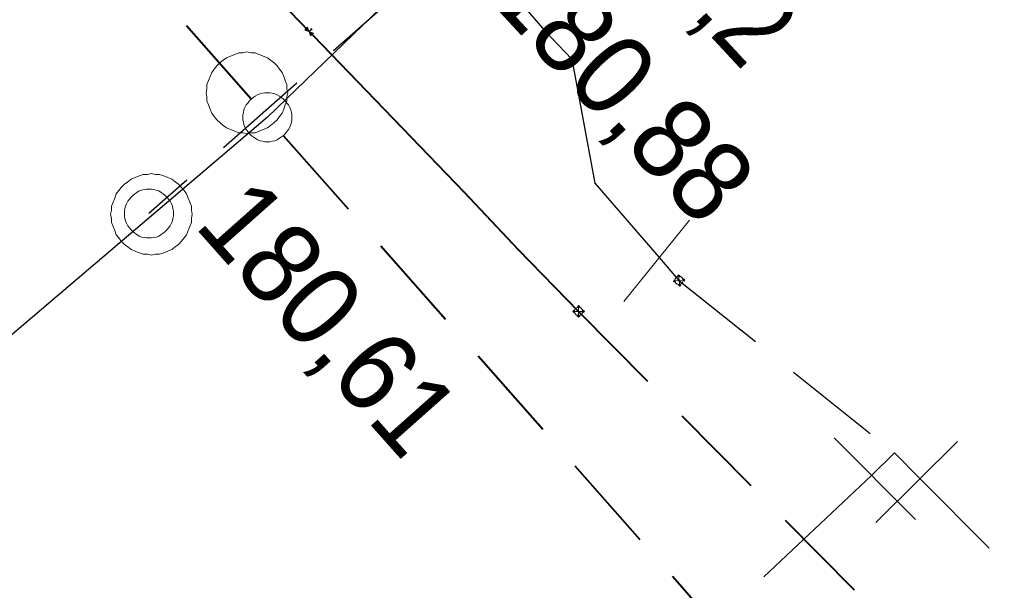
# Model space of a CAD drawing. Extents: x -740851 to -738888, y -1041382 to -1040235.
# Drawn here: x -739704.31 to -739692.27, y -1040578.08 to -1040571.08 of the extents above; entities that cross this region are included whole.
import ezdxf

# ---------------------------------------------------------------- set-up
doc = ezdxf.new("R2010")
doc.units = 0
doc.header["$LTSCALE"] = 0.4
doc.linetypes.add('MEDIUM_DASHED', pattern=[4.5, 3, -1.5])
for name, color, linetype, lineweight in [('18', 7, 'Continuous', 13), ('20', 7, 'MEDIUM_DASHED', 25), ('8', 7, 'Continuous', 13)]:
    doc.layers.add(name, color=color, linetype=linetype, lineweight=lineweight)

msp = doc.modelspace()

# ---------------------------------------------------------------- linework, layer by layer
at = {"layer": '18', "lineweight": 25}
msp.add_line((-739699.51, -1040570.57), (-739701.28, -1040572.28), dxfattribs=at)
at = {"layer": '18', "linetype": 'MEDIUM_DASHED', "lineweight": 40}
msp.add_lwpolyline([(-739669.06, -1040610.98), (-739674.7, -1040603.39), (-739681.24, -1040595.01), (-739703.155, -1040570.156)], dxfattribs=at)
at = {"layer": '18'}
for points in [[(-739701.03, -1040571.98), (-739701.04, -1040571.93), (-739701.04, -1040571.88), (-739701.06, -1040571.83), (-739701.08, -1040571.78), (-739701.1, -1040571.73), (-739701.13, -1040571.69), (-739701.16, -1040571.65), (-739701.2, -1040571.61), (-739701.24, -1040571.58), (-739701.28, -1040571.55), (-739701.33, -1040571.53), (-739701.38, -1040571.51), (-739701.43, -1040571.49), (-739701.48, -1040571.49), (-739701.53, -1040571.48), (-739701.58, -1040571.49), (-739701.63, -1040571.49), (-739701.68, -1040571.51), (-739701.73, -1040571.53), (-739701.78, -1040571.55), (-739701.82, -1040571.58), (-739701.86, -1040571.61), (-739701.9, -1040571.65), (-739701.93, -1040571.69), (-739701.96, -1040571.73), (-739701.98, -1040571.78), (-739702, -1040571.83), (-739702.02, -1040571.88), (-739702.02, -1040571.93), (-739702.03, -1040571.98), (-739702.02, -1040572.03), (-739702.02, -1040572.08), (-739702, -1040572.13), (-739701.98, -1040572.18), (-739701.96, -1040572.23), (-739701.93, -1040572.27), (-739701.9, -1040572.31), (-739701.86, -1040572.35), (-739701.82, -1040572.38), (-739701.78, -1040572.41), (-739701.73, -1040572.43), (-739701.68, -1040572.45), (-739701.63, -1040572.47), (-739701.58, -1040572.47), (-739701.53, -1040572.48), (-739701.48, -1040572.47), (-739701.43, -1040572.47), (-739701.38, -1040572.45), (-739701.33, -1040572.43), (-739701.28, -1040572.41), (-739701.24, -1040572.38), (-739701.2, -1040572.35), (-739701.16, -1040572.31), (-739701.13, -1040572.27), (-739701.1, -1040572.23), (-739701.08, -1040572.18), (-739701.06, -1040572.13), (-739701.04, -1040572.08), (-739701.04, -1040572.03)], [(-739700.98, -1040572.28), (-739700.98, -1040572.25), (-739700.986, -1040572.22), (-739700.992, -1040572.19), (-739701.004, -1040572.16), (-739701.022, -1040572.13), (-739701.04, -1040572.106), (-739701.058, -1040572.082), (-739701.082, -1040572.058), (-739701.106, -1040572.04), (-739701.13, -1040572.022), (-739701.16, -1040572.004), (-739701.19, -1040571.992), (-739701.22, -1040571.986), (-739701.25, -1040571.98), (-739701.28, -1040571.98), (-739701.31, -1040571.98), (-739701.34, -1040571.986), (-739701.37, -1040571.992), (-739701.4, -1040572.004), (-739701.43, -1040572.022), (-739701.454, -1040572.04), (-739701.478, -1040572.058), (-739701.502, -1040572.082), (-739701.52, -1040572.106), (-739701.538, -1040572.13), (-739701.556, -1040572.16), (-739701.568, -1040572.19), (-739701.574, -1040572.22), (-739701.58, -1040572.25), (-739701.58, -1040572.28), (-739701.58, -1040572.31), (-739701.574, -1040572.34), (-739701.568, -1040572.37), (-739701.556, -1040572.4), (-739701.538, -1040572.43), (-739701.52, -1040572.454), (-739701.502, -1040572.478), (-739701.478, -1040572.502), (-739701.454, -1040572.52), (-739701.43, -1040572.538), (-739701.4, -1040572.556), (-739701.37, -1040572.568), (-739701.34, -1040572.574), (-739701.31, -1040572.58), (-739701.28, -1040572.58), (-739701.25, -1040572.58), (-739701.22, -1040572.574), (-739701.19, -1040572.568), (-739701.16, -1040572.556), (-739701.13, -1040572.538), (-739701.106, -1040572.52), (-739701.082, -1040572.502), (-739701.058, -1040572.478), (-739701.04, -1040572.454), (-739701.022, -1040572.43), (-739701.004, -1040572.4), (-739700.992, -1040572.37), (-739700.986, -1040572.34), (-739700.98, -1040572.31)], [(-739702.2, -1040573.47), (-739702.21, -1040573.42), (-739702.21, -1040573.37), (-739702.23, -1040573.32), (-739702.25, -1040573.27), (-739702.27, -1040573.22), (-739702.3, -1040573.18), (-739702.33, -1040573.14), (-739702.37, -1040573.1), (-739702.41, -1040573.07), (-739702.45, -1040573.04), (-739702.5, -1040573.02), (-739702.55, -1040573), (-739702.6, -1040572.98), (-739702.65, -1040572.98), (-739702.7, -1040572.97), (-739702.75, -1040572.98), (-739702.8, -1040572.98), (-739702.85, -1040573), (-739702.9, -1040573.02), (-739702.95, -1040573.04), (-739702.99, -1040573.07), (-739703.03, -1040573.1), (-739703.07, -1040573.14), (-739703.1, -1040573.18), (-739703.13, -1040573.22), (-739703.15, -1040573.27), (-739703.17, -1040573.32), (-739703.19, -1040573.37), (-739703.19, -1040573.42), (-739703.2, -1040573.47), (-739703.19, -1040573.52), (-739703.19, -1040573.57), (-739703.17, -1040573.62), (-739703.15, -1040573.67), (-739703.13, -1040573.72), (-739703.1, -1040573.76), (-739703.07, -1040573.8), (-739703.03, -1040573.84), (-739702.99, -1040573.87), (-739702.95, -1040573.9), (-739702.9, -1040573.92), (-739702.85, -1040573.94), (-739702.8, -1040573.96), (-739702.75, -1040573.96), (-739702.7, -1040573.97), (-739702.65, -1040573.96), (-739702.6, -1040573.96), (-739702.55, -1040573.94), (-739702.5, -1040573.92), (-739702.45, -1040573.9), (-739702.41, -1040573.87), (-739702.37, -1040573.84), (-739702.33, -1040573.8), (-739702.3, -1040573.76), (-739702.27, -1040573.72), (-739702.25, -1040573.67), (-739702.23, -1040573.62), (-739702.21, -1040573.57), (-739702.21, -1040573.52)], [(-739702.43, -1040573.46), (-739702.43, -1040573.43), (-739702.436, -1040573.4), (-739702.442, -1040573.37), (-739702.454, -1040573.34), (-739702.472, -1040573.31), (-739702.49, -1040573.286), (-739702.508, -1040573.262), (-739702.532, -1040573.238), (-739702.556, -1040573.22), (-739702.58, -1040573.202), (-739702.61, -1040573.184), (-739702.64, -1040573.172), (-739702.67, -1040573.166), (-739702.7, -1040573.16), (-739702.73, -1040573.16), (-739702.76, -1040573.16), (-739702.79, -1040573.166), (-739702.82, -1040573.172), (-739702.85, -1040573.184), (-739702.88, -1040573.202), (-739702.904, -1040573.22), (-739702.928, -1040573.238), (-739702.952, -1040573.262), (-739702.97, -1040573.286), (-739702.988, -1040573.31), (-739703.006, -1040573.34), (-739703.018, -1040573.37), (-739703.024, -1040573.4), (-739703.03, -1040573.43), (-739703.03, -1040573.46), (-739703.03, -1040573.49), (-739703.024, -1040573.52), (-739703.018, -1040573.55), (-739703.006, -1040573.58), (-739702.988, -1040573.61), (-739702.97, -1040573.634), (-739702.952, -1040573.658), (-739702.928, -1040573.682), (-739702.904, -1040573.7), (-739702.88, -1040573.718), (-739702.85, -1040573.736), (-739702.82, -1040573.748), (-739702.79, -1040573.754), (-739702.76, -1040573.76), (-739702.73, -1040573.76), (-739702.7, -1040573.76), (-739702.67, -1040573.754), (-739702.64, -1040573.748), (-739702.61, -1040573.736), (-739702.58, -1040573.718), (-739702.556, -1040573.7), (-739702.532, -1040573.682), (-739702.508, -1040573.658), (-739702.49, -1040573.634), (-739702.472, -1040573.61), (-739702.454, -1040573.58), (-739702.442, -1040573.55), (-739702.436, -1040573.52), (-739702.43, -1040573.49)]]:
    msp.add_lwpolyline(points, close=True, dxfattribs=at)
at = {"layer": '18', "lineweight": 25}
msp.add_lwpolyline([(-739701.28, -1040572.28), (-739707.2, -1040577.32), (-739710.924, -1040580.488)], dxfattribs=at)
at = {"layer": '20'}
msp.add_lwpolyline([(-739674.14, -1040548.21), (-739688.774, -1040561.14), (-739702.73, -1040573.46)], dxfattribs=at)
at = {"layer": '8'}
for p, q in [((-739700.769, -1040571.23), (-739700.734, -1040571.195)), ((-739696.913, -1040574.54), (-739696.112, -1040573.54)), ((-739696.246, -1040574.21), (-739696.258, -1040574.225)), ((-739696.246, -1040574.21), (-739696.23, -1040574.35)), ((-739696.246, -1040574.21), (-739696.23, -1040574.222)), ((-739696.308, -1040574.288), (-739696.168, -1040574.272)), ((-739696.308, -1040574.288), (-739696.296, -1040574.272)), ((-739696.308, -1040574.288), (-739696.293, -1040574.3)), ((-739696.23, -1040574.35), (-739696.246, -1040574.338)), ((-739696.23, -1040574.35), (-739696.218, -1040574.335)), ((-739696.168, -1040574.272), (-739696.184, -1040574.26)), ((-739696.168, -1040574.272), (-739696.18, -1040574.288)), ((-739697.469, -1040574.589), (-739697.483, -1040574.603)), ((-739697.469, -1040574.589), (-739697.469, -1040574.731)), ((-739697.469, -1040574.589), (-739697.455, -1040574.604)), ((-739697.54, -1040574.66), (-739697.526, -1040574.646)), ((-739697.54, -1040574.66), (-739697.398, -1040574.66)), ((-739697.54, -1040574.66), (-739697.526, -1040574.674)), ((-739697.398, -1040574.66), (-739697.413, -1040574.674)), ((-739697.398, -1040574.66), (-739697.412, -1040574.646)), ((-739697.469, -1040574.731), (-739697.484, -1040574.716)), ((-739697.469, -1040574.731), (-739697.455, -1040574.717)), ((-739693.344, -1040577.21), (-739694.337, -1040576.21)), ((-739693.826, -1040577.247), (-739692.826, -1040576.253))]:
    msp.add_line(p, q, dxfattribs=at)
at = {"layer": '8', "lineweight": 25}
for p, q in [((-739696.48, -1040574), (-739696.24, -1040574.28)), ((-739693.601, -1040576.393), (-739693.88, -1040576.67)), ((-739693.88, -1040576.67), (-739695.2, -1040577.915))]:
    msp.add_line(p, q, dxfattribs=at)
at = {"layer": '8', "lineweight": 40}
for points in [[(-739703.68, -1040568.1), (-739703.46, -1040568.39), (-739702.71, -1040569.21), (-739702.32, -1040569.62), (-739700.77, -1040571.23)], [(-739700.77, -1040571.23), (-739700.72, -1040571.28), (-739698.87, -1040573.2), (-739698.21, -1040573.9), (-739697.47, -1040574.66)]]:
    msp.add_lwpolyline(points, dxfattribs=at)
at = {"layer": '8', "lineweight": 25}
msp.add_lwpolyline([(-739698.48, -1040570.53), (-739698.38, -1040570.64), (-739697.88, -1040571.22), (-739697.55, -1040571.57), (-739697.27, -1040573.09), (-739696.48, -1040574)], dxfattribs=at)
at = {"layer": '8'}
for points in [[(-739700.821, -1040571.212), (-739700.717, -1040571.248), (-739700.751, -1040571.282), (-739700.787, -1040571.178)], [(-739700.817, -1040571.21), (-739700.773, -1040571.226), (-739700.789, -1040571.182)], [(-739700.814, -1040571.209), (-739700.789, -1040571.185), (-739700.777, -1040571.222)], [(-739700.809, -1040571.208), (-739700.791, -1040571.19), (-739700.781, -1040571.218)], [(-739700.805, -1040571.207), (-739700.792, -1040571.194), (-739700.785, -1040571.214)], [(-739700.802, -1040571.206), (-739700.793, -1040571.197), (-739700.789, -1040571.21)], [(-739700.797, -1040571.205), (-739700.794, -1040571.202), (-739700.792, -1040571.207)], [(-739700.721, -1040571.25), (-739700.749, -1040571.278), (-739700.765, -1040571.234)], [(-739700.748, -1040571.275), (-739700.724, -1040571.251), (-739700.761, -1040571.238)], [(-739700.747, -1040571.27), (-739700.729, -1040571.252), (-739700.757, -1040571.242)], [(-739700.746, -1040571.266), (-739700.733, -1040571.253), (-739700.753, -1040571.246)], [(-739700.745, -1040571.263), (-739700.736, -1040571.254), (-739700.749, -1040571.25)], [(-739700.744, -1040571.258), (-739700.741, -1040571.255), (-739700.746, -1040571.253)], [(-739696.199, -1040574.311), (-739696.196, -1040574.307), (-739696.194, -1040574.303), (-739696.191, -1040574.298), (-739696.19, -1040574.293), (-739696.189, -1040574.287), (-739696.189, -1040574.282), (-739696.189, -1040574.277), (-739696.189, -1040574.272), (-739696.191, -1040574.267), (-739696.192, -1040574.262), (-739696.194, -1040574.257), (-739696.196, -1040574.252), (-739696.2, -1040574.248), (-739696.203, -1040574.244), (-739696.207, -1040574.241), (-739696.211, -1040574.238), (-739696.215, -1040574.235), (-739696.22, -1040574.233), (-739696.225, -1040574.232), (-739696.231, -1040574.231), (-739696.236, -1040574.231), (-739696.241, -1040574.23), (-739696.246, -1040574.231), (-739696.251, -1040574.232), (-739696.256, -1040574.234), (-739696.262, -1040574.236), (-739696.266, -1040574.238), (-739696.27, -1040574.242), (-739696.274, -1040574.245), (-739696.277, -1040574.249), (-739696.28, -1040574.253), (-739696.283, -1040574.257), (-739696.285, -1040574.262), (-739696.287, -1040574.267), (-739696.287, -1040574.273), (-739696.288, -1040574.278), (-739696.288, -1040574.283), (-739696.287, -1040574.288), (-739696.286, -1040574.293), (-739696.285, -1040574.298), (-739696.283, -1040574.303), (-739696.28, -1040574.308), (-739696.277, -1040574.312), (-739696.273, -1040574.316), (-739696.269, -1040574.319), (-739696.266, -1040574.322), (-739696.261, -1040574.324), (-739696.256, -1040574.327), (-739696.251, -1040574.328), (-739696.246, -1040574.329), (-739696.241, -1040574.329), (-739696.236, -1040574.329), (-739696.23, -1040574.329), (-739696.225, -1040574.328), (-739696.22, -1040574.326), (-739696.215, -1040574.324), (-739696.21, -1040574.322), (-739696.206, -1040574.318), (-739696.202, -1040574.315)], [(-739697.434, -1040574.696), (-739697.43, -1040574.692), (-739697.428, -1040574.688), (-739697.425, -1040574.684), (-739697.423, -1040574.679), (-739697.421, -1040574.673), (-739697.42, -1040574.668), (-739697.42, -1040574.663), (-739697.42, -1040574.657), (-739697.42, -1040574.652), (-739697.421, -1040574.648), (-739697.422, -1040574.642), (-739697.424, -1040574.637), (-739697.427, -1040574.633), (-739697.43, -1040574.628), (-739697.434, -1040574.625), (-739697.437, -1040574.621), (-739697.441, -1040574.618), (-739697.446, -1040574.616), (-739697.45, -1040574.613), (-739697.456, -1040574.612), (-739697.461, -1040574.611), (-739697.466, -1040574.611), (-739697.472, -1040574.61), (-739697.477, -1040574.611), (-739697.482, -1040574.612), (-739697.487, -1040574.613), (-739697.492, -1040574.615), (-739697.496, -1040574.618), (-739697.501, -1040574.621), (-739697.504, -1040574.624), (-739697.508, -1040574.628), (-739697.511, -1040574.632), (-739697.514, -1040574.636), (-739697.516, -1040574.641), (-739697.517, -1040574.647), (-739697.518, -1040574.652), (-739697.519, -1040574.657), (-739697.519, -1040574.663), (-739697.518, -1040574.668), (-739697.517, -1040574.672), (-739697.516, -1040574.678), (-739697.514, -1040574.683), (-739697.511, -1040574.687), (-739697.508, -1040574.692), (-739697.505, -1040574.695), (-739697.501, -1040574.699), (-739697.497, -1040574.702), (-739697.493, -1040574.704), (-739697.488, -1040574.707), (-739697.482, -1040574.708), (-739697.477, -1040574.709), (-739697.472, -1040574.709), (-739697.467, -1040574.71), (-739697.462, -1040574.709), (-739697.457, -1040574.708), (-739697.451, -1040574.707), (-739697.446, -1040574.705), (-739697.442, -1040574.702), (-739697.437, -1040574.699)]]:
    msp.add_lwpolyline(points, close=True, dxfattribs=at)
msp.add_lwpolyline([(-739700.751, -1040571.196), (-739700.734, -1040571.195), (-739700.734, -1040571.213)], dxfattribs=at)
at = {"layer": '8', "linetype": 'MEDIUM_DASHED', "lineweight": 25}
for points in [[(-739696.24, -1040574.28), (-739693.601, -1040576.393), (-739693.286, -1040576.71)], [(-739693.286, -1040576.71), (-739686.808, -1040583.233), (-739625.283, -1040665.839), (-739571.664, -1040740.804), (-739523.94, -1040810.745), (-739502.47, -1040846.1), (-739496.554, -1040855.122)]]:
    msp.add_lwpolyline(points, dxfattribs=at)
at = {"layer": '8', "linetype": 'MEDIUM_DASHED', "lineweight": 40}
msp.add_lwpolyline([(-739697.47, -1040574.66), (-739686.88, -1040585.368), (-739626.36, -1040666.625), (-739572.757, -1040741.567), (-739553.461, -1040769.846), (-739533.944, -1040772.907), (-739491.526, -1040761.298), (-739476.568, -1040755.167), (-739461.603, -1040761.762), (-739415.52, -1040777.67)], dxfattribs=at)

# ---------------------------------------------------------------- texts
at = {"layer": '18'}
for s, rotation, width, p in [('181,2', 312.786, 0.85, (-739697.38, -1040569.639)), ('180,88', 312.785, 0.95, (-739698.607, -1040570.806)), ('180,61', 311.649, 0.95, (-739702.188, -1040573.611))]:
    msp.add_text(s, height=1, rotation=rotation, dxfattribs=dict(at, width=width)).set_placement(p)

doc.saveas('drawing.dxf')
